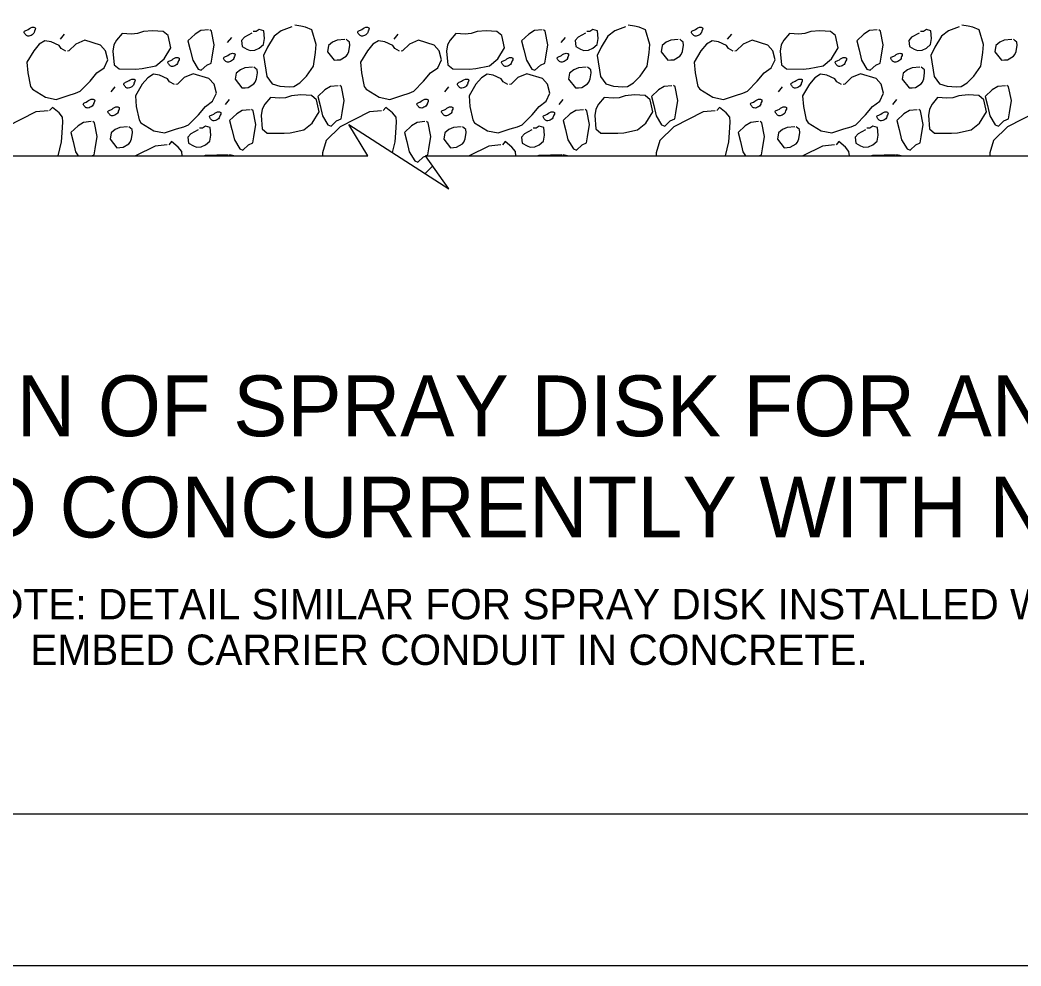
# Model space of a CAD drawing. Extents: x 3239 to 4230, y -4276 to -2494.
# Drawn here: x 3405.7 to 3504.5, y -4276.3 to -4182.9 of the extents above; entities that cross this region are included whole.
import ezdxf

# ---------------------------------------------------------------- set-up
doc = ezdxf.new("R2010")
doc.units = 0
doc.layers.add('2', color=7, linetype='Continuous')
doc.layers.add('PLT-BNDY', color=7, linetype='Continuous')

msp = doc.modelspace()

# ---------------------------------------------------------------- linework, layer by layer
at = {"layer": '2'}
for p, q in [((3440.07, -4196.29), (3438.177, -4193.169)), ((3438.177, -4193.169), (3448.046, -4199.536)), ((3325.856, -4196.29), (3440.07, -4196.29)), ((3448.046, -4199.536), (3445.738, -4196.29)), ((3445.738, -4196.29), (3572.037, -4196.29)), ((3445.705, -4198.026), (3446.446, -4197.285)), ((4065.025, -4261.289), (3279.025, -4261.289))]:
    msp.add_line(p, q, dxfattribs=at)
for points in [[(3432.546, -4183.543), (3431.513, -4183.938), (3430.817, -4184.456), (3430.151, -4185.561), (3429.764, -4186.357), (3430.098, -4188.442), (3430.62, -4189.159), (3431.381, -4189.398), (3432.302, -4189.469), (3432.757, -4189.429), (3433.335, -4189.075), (3434.017, -4188.404), (3434.695, -4187.429), (3434.88, -4186.063), (3434.967, -4185.293), (3434.533, -4183.826), (3433.9, -4183.578), (3433.434, -4183.465), (3432.836, -4183.365)], [(3465.49, -4183.543), (3464.456, -4183.938), (3463.761, -4184.456), (3463.095, -4185.561), (3462.708, -4186.357), (3463.042, -4188.442), (3463.563, -4189.159), (3464.325, -4189.398), (3465.246, -4189.469), (3465.701, -4189.429), (3466.279, -4189.075), (3466.961, -4188.404), (3467.638, -4187.429), (3467.824, -4186.063), (3467.91, -4185.293), (3467.477, -4183.826), (3466.844, -4183.578), (3466.377, -4183.465), (3465.779, -4183.365)], [(3498.433, -4183.543), (3497.4, -4183.938), (3496.705, -4184.456), (3496.039, -4185.561), (3495.651, -4186.357), (3495.985, -4188.442), (3496.507, -4189.159), (3497.269, -4189.398), (3498.189, -4189.469), (3498.645, -4189.429), (3499.223, -4189.075), (3499.905, -4188.404), (3500.582, -4187.429), (3500.768, -4186.063), (3500.854, -4185.293), (3500.42, -4183.826), (3499.788, -4183.578), (3499.321, -4183.465), (3498.723, -4183.365)], [(3410.082, -4184.25), (3409.666, -4184.745)], [(3416.726, -4184.259), (3415.805, -4184.188), (3415.252, -4184.847), (3414.989, -4185.327), (3414.891, -4185.944), (3415.009, -4187.286), (3415.502, -4187.7), (3417.16, -4187.708), (3417.764, -4187.655), (3419.113, -4187.384), (3419.948, -4186.702), (3420.614, -4185.597), (3420.356, -4184.4), (3419.862, -4183.984), (3418.811, -4183.925), (3417.903, -4184.004), (3417.31, -4184.208), (3416.726, -4184.259)], [(3424.313, -4183.849), (3423.554, -4183.915), (3422.998, -4184.269), (3422.293, -4184.92), (3422.523, -4185.814), (3422.766, -4186.839), (3423.299, -4187.708), (3423.615, -4187.832), (3424.158, -4187.328), (3424.601, -4187.135), (3424.7, -4186.539), (3424.897, -4185.301), (3424.628, -4183.975), (3424.464, -4183.835)], [(3426.586, -4184.598), (3426.17, -4185.093)], [(3428.598, -4184.178), (3427.867, -4184.547), (3427.593, -4184.877), (3427.646, -4185.481), (3428.126, -4185.744), (3428.442, -4185.87), (3428.896, -4185.831), (3429.336, -4185.639), (3429.742, -4185.298), (3429.841, -4184.68), (3429.775, -4183.923), (3429.33, -4183.809), (3429.04, -4183.988), (3428.737, -4184.014)], [(3443.026, -4184.25), (3442.61, -4184.745)], [(3449.67, -4184.259), (3448.749, -4184.188), (3448.196, -4184.847), (3447.933, -4185.327), (3447.835, -4185.944), (3447.952, -4187.286), (3448.446, -4187.7), (3450.103, -4187.708), (3450.708, -4187.655), (3452.057, -4187.384), (3452.892, -4186.702), (3453.558, -4185.597), (3453.299, -4184.4), (3452.806, -4183.984), (3451.754, -4183.925), (3450.847, -4184.004), (3450.254, -4184.208), (3449.67, -4184.259)], [(3457.257, -4183.849), (3456.498, -4183.915), (3455.942, -4184.269), (3455.236, -4184.92), (3455.466, -4185.814), (3455.71, -4186.839), (3456.243, -4187.708), (3456.559, -4187.832), (3457.102, -4187.328), (3457.544, -4187.135), (3457.644, -4186.539), (3457.841, -4185.301), (3457.571, -4183.975), (3457.407, -4183.835)], [(3459.53, -4184.598), (3459.114, -4185.093)], [(3461.541, -4184.178), (3460.811, -4184.547), (3460.536, -4184.877), (3460.589, -4185.481), (3461.07, -4185.744), (3461.386, -4185.87), (3461.84, -4185.831), (3462.28, -4185.639), (3462.686, -4185.298), (3462.785, -4184.68), (3462.719, -4183.923), (3462.273, -4183.809), (3461.984, -4183.988), (3461.681, -4184.014)], [(3475.97, -4184.25), (3475.554, -4184.745)], [(3482.613, -4184.259), (3481.693, -4184.188), (3481.14, -4184.847), (3480.876, -4185.327), (3480.779, -4185.944), (3480.896, -4187.286), (3481.389, -4187.7), (3483.047, -4187.708), (3483.651, -4187.655), (3485.001, -4187.384), (3485.836, -4186.702), (3486.501, -4185.597), (3486.243, -4184.4), (3485.75, -4183.984), (3484.698, -4183.925), (3483.791, -4184.004), (3483.198, -4184.208), (3482.613, -4184.259)], [(3490.358, -4183.849), (3489.599, -4183.915), (3489.043, -4184.269), (3488.338, -4184.92), (3488.568, -4185.814), (3488.811, -4186.839), (3489.344, -4187.708), (3489.66, -4187.832), (3490.203, -4187.328), (3490.645, -4187.135), (3490.745, -4186.539), (3490.942, -4185.301), (3490.672, -4183.975), (3490.508, -4183.835)], [(3494.485, -4184.178), (3493.755, -4184.547), (3493.48, -4184.877), (3493.533, -4185.481), (3494.013, -4185.744), (3494.33, -4185.87), (3494.783, -4185.831), (3495.224, -4185.639), (3495.629, -4185.298), (3495.729, -4184.68), (3495.663, -4183.923), (3495.217, -4183.809), (3494.927, -4183.988), (3494.624, -4184.014)], [(3410.251, -4185.945), (3409.77, -4185.681), (3409.592, -4185.393), (3408.795, -4185.004), (3408.178, -4184.906), (3407.62, -4185.261), (3407.066, -4185.918), (3406.4, -4187.022), (3406.493, -4188.082), (3406.765, -4189.432), (3406.94, -4189.7), (3408.23, -4190.501), (3409.295, -4190.714), (3410.48, -4190.304), (3411.202, -4190.089), (3411.643, -4189.899), (3412.625, -4188.919), (3413.294, -4188.098), (3414.011, -4187.578), (3414.398, -4186.782), (3414.17, -4185.907), (3413.663, -4185.341), (3412.119, -4184.867), (3411.236, -4185.25), (3410.532, -4185.92), (3410.403, -4185.931)], [(3437.773, -4184.782), (3437.016, -4184.848), (3436.576, -4185.04), (3436.17, -4185.38), (3436.07, -4185.999), (3436.733, -4186.835), (3437.036, -4186.809), (3437.339, -4186.782), (3437.918, -4186.448), (3438.058, -4186.282), (3438.182, -4185.968), (3438.279, -4185.349), (3438.253, -4185.046), (3438.089, -4184.908), (3437.925, -4184.769)], [(3443.194, -4185.945), (3442.714, -4185.681), (3442.535, -4185.393), (3441.739, -4185.004), (3441.121, -4184.906), (3440.563, -4185.261), (3440.01, -4185.918), (3439.344, -4187.022), (3439.437, -4188.082), (3439.709, -4189.432), (3439.884, -4189.7), (3441.174, -4190.501), (3442.238, -4190.714), (3443.424, -4190.304), (3444.146, -4190.089), (3444.587, -4189.899), (3445.569, -4188.919), (3446.238, -4188.098), (3446.955, -4187.578), (3447.342, -4186.782), (3447.114, -4185.907), (3446.607, -4185.341), (3445.062, -4184.867), (3444.18, -4185.25), (3443.476, -4185.92), (3443.347, -4185.931)], [(3470.716, -4184.782), (3469.96, -4184.848), (3469.519, -4185.04), (3469.114, -4185.38), (3469.014, -4185.999), (3469.676, -4186.835), (3469.979, -4186.809), (3470.283, -4186.782), (3470.862, -4186.448), (3471.001, -4186.282), (3471.126, -4185.968), (3471.223, -4185.349), (3471.197, -4185.046), (3471.033, -4184.908), (3470.869, -4184.769)], [(3476.138, -4185.945), (3475.658, -4185.681), (3475.479, -4185.393), (3474.683, -4185.004), (3474.065, -4184.906), (3473.507, -4185.261), (3472.954, -4185.918), (3472.288, -4187.022), (3472.381, -4188.082), (3472.652, -4189.432), (3472.828, -4189.7), (3474.117, -4190.501), (3475.182, -4190.714), (3476.368, -4190.304), (3477.09, -4190.089), (3477.53, -4189.899), (3478.512, -4188.919), (3479.181, -4188.098), (3479.898, -4187.578), (3480.286, -4186.782), (3480.058, -4185.907), (3479.551, -4185.341), (3478.006, -4184.867), (3477.123, -4185.25), (3476.42, -4185.92), (3476.291, -4185.931)], [(3503.66, -4184.782), (3502.904, -4184.848), (3502.463, -4185.04), (3502.057, -4185.38), (3501.958, -4185.999), (3502.62, -4186.835), (3502.923, -4186.809), (3503.226, -4186.782), (3503.806, -4186.448), (3503.945, -4186.282), (3504.069, -4185.968), (3504.167, -4185.349), (3504.14, -4185.046), (3503.977, -4184.908), (3503.813, -4184.769)], [(3428.668, -4187.521), (3427.911, -4187.587), (3427.469, -4187.779), (3427.04, -4188.099), (3426.942, -4188.718), (3427.626, -4189.574), (3427.929, -4189.548), (3428.232, -4189.521), (3428.812, -4189.165), (3428.927, -4189.002), (3429.053, -4188.685), (3429.151, -4188.068), (3429.126, -4187.786), (3428.963, -4187.649), (3428.797, -4187.51)], [(3461.611, -4187.521), (3460.855, -4187.587), (3460.413, -4187.779), (3459.983, -4188.099), (3459.886, -4188.718), (3460.57, -4189.574), (3460.873, -4189.548), (3461.176, -4189.521), (3461.755, -4189.165), (3461.871, -4189.002), (3461.997, -4188.685), (3462.095, -4188.068), (3462.07, -4187.786), (3461.906, -4187.649), (3461.741, -4187.51)], [(3494.555, -4187.521), (3493.798, -4187.587), (3493.356, -4187.779), (3492.927, -4188.099), (3492.83, -4188.718), (3493.513, -4189.574), (3493.816, -4189.548), (3494.119, -4189.521), (3494.699, -4189.165), (3494.815, -4189.002), (3494.941, -4188.685), (3495.038, -4188.068), (3495.014, -4187.786), (3494.85, -4187.649), (3494.684, -4187.51)], [(3420.951, -4189.242), (3420.471, -4188.979), (3420.292, -4188.689), (3419.497, -4188.323), (3418.88, -4188.225), (3418.322, -4188.58), (3417.767, -4189.215), (3417.103, -4190.341), (3417.196, -4191.401), (3417.465, -4192.729), (3417.642, -4193.019), (3418.93, -4193.799), (3419.995, -4194.011), (3421.181, -4193.602), (3421.905, -4193.409), (3422.345, -4193.216), (3423.325, -4192.216), (3424.016, -4191.393), (3424.711, -4190.874), (3425.101, -4190.099), (3424.871, -4189.205), (3424.364, -4188.638), (3422.819, -4188.186), (3421.936, -4188.545), (3421.254, -4189.216), (3421.102, -4189.229)], [(3453.895, -4189.242), (3453.415, -4188.979), (3453.236, -4188.689), (3452.441, -4188.323), (3451.824, -4188.225), (3451.266, -4188.58), (3450.711, -4189.215), (3450.047, -4190.341), (3450.139, -4191.401), (3450.409, -4192.729), (3450.586, -4193.019), (3451.874, -4193.799), (3452.939, -4194.011), (3454.125, -4193.602), (3454.848, -4193.409), (3455.289, -4193.216), (3456.269, -4192.216), (3456.96, -4191.393), (3457.655, -4190.874), (3458.044, -4190.099), (3457.814, -4189.205), (3457.308, -4188.638), (3455.763, -4188.186), (3454.88, -4188.545), (3454.198, -4189.216), (3454.045, -4189.229)], [(3486.839, -4189.242), (3486.358, -4188.979), (3486.18, -4188.689), (3485.385, -4188.323), (3484.768, -4188.225), (3484.209, -4188.58), (3483.654, -4189.215), (3482.99, -4190.341), (3483.083, -4191.401), (3483.353, -4192.729), (3483.53, -4193.019), (3484.818, -4193.799), (3485.883, -4194.011), (3487.068, -4193.602), (3487.792, -4193.409), (3488.233, -4193.216), (3489.213, -4192.216), (3489.903, -4191.393), (3490.599, -4190.874), (3490.988, -4190.099), (3490.758, -4189.205), (3490.251, -4188.638), (3488.707, -4188.186), (3487.824, -4188.545), (3487.142, -4189.216), (3486.989, -4189.229)], [(3415.092, -4189.474), (3414.677, -4189.969)], [(3437.13, -4189.352), (3436.372, -4189.418), (3435.816, -4189.772), (3435.11, -4190.423), (3435.34, -4191.317), (3435.583, -4192.342), (3436.117, -4193.211), (3436.433, -4193.335), (3436.976, -4192.831), (3437.418, -4192.639), (3437.518, -4192.043), (3437.715, -4190.804), (3437.445, -4189.478), (3437.281, -4189.339)], [(3448.036, -4189.474), (3447.62, -4189.969)], [(3470.074, -4189.352), (3469.316, -4189.418), (3468.759, -4189.772), (3468.054, -4190.423), (3468.284, -4191.317), (3468.527, -4192.342), (3469.06, -4193.211), (3469.377, -4193.335), (3469.92, -4192.831), (3470.362, -4192.639), (3470.461, -4192.043), (3470.658, -4190.804), (3470.389, -4189.478), (3470.225, -4189.339)], [(3480.98, -4189.474), (3480.564, -4189.969)], [(3503.018, -4189.352), (3502.259, -4189.418), (3501.703, -4189.772), (3500.998, -4190.423), (3501.228, -4191.317), (3501.471, -4192.342), (3502.004, -4193.211), (3502.32, -4193.335), (3502.863, -4192.831), (3503.305, -4192.639), (3503.405, -4192.043), (3503.602, -4190.804), (3503.333, -4189.478), (3503.169, -4189.339)], [(3431.354, -4190.598), (3430.434, -4190.527), (3429.881, -4191.186), (3429.618, -4191.666), (3429.52, -4192.283), (3429.637, -4193.625), (3430.13, -4194.039), (3431.788, -4194.047), (3432.392, -4193.994), (3433.742, -4193.723), (3434.577, -4193.041), (3435.243, -4191.936), (3434.984, -4190.739), (3434.491, -4190.323), (3433.439, -4190.264), (3432.532, -4190.343), (3431.939, -4190.547), (3431.354, -4190.598)], [(3464.298, -4190.598), (3463.378, -4190.527), (3462.825, -4191.186), (3462.561, -4191.666), (3462.464, -4192.283), (3462.581, -4193.625), (3463.074, -4194.039), (3464.732, -4194.047), (3465.336, -4193.994), (3466.686, -4193.723), (3467.52, -4193.041), (3468.186, -4191.936), (3467.928, -4190.739), (3467.434, -4190.323), (3466.383, -4190.264), (3465.476, -4190.343), (3464.883, -4190.547), (3464.298, -4190.598)], [(3497.242, -4190.598), (3496.321, -4190.527), (3495.768, -4191.186), (3495.505, -4191.666), (3495.407, -4192.283), (3495.525, -4193.625), (3496.018, -4194.039), (3497.676, -4194.047), (3498.28, -4193.994), (3499.629, -4193.723), (3500.464, -4193.041), (3501.13, -4191.936), (3500.872, -4190.739), (3500.378, -4190.323), (3499.327, -4190.264), (3498.419, -4190.343), (3497.827, -4190.547), (3497.242, -4190.598)], [(3409.48, -4196.29), (3409.814, -4194.896), (3409.887, -4193.995), (3409.947, -4192.922), (3409.907, -4192.469), (3409.564, -4192.041), (3408.907, -4191.51), (3408.629, -4191.818)], [(3426.377, -4190.728), (3425.961, -4191.223)], [(3442.503, -4195.96), (3442.758, -4194.896), (3442.831, -4193.995), (3442.891, -4192.922), (3442.851, -4192.469), (3442.508, -4192.041), (3441.851, -4191.51), (3441.572, -4191.818)], [(3459.321, -4190.728), (3458.905, -4191.223)], [(3475.367, -4196.29), (3475.702, -4194.896), (3475.775, -4193.995), (3475.834, -4192.922), (3475.795, -4192.469), (3475.452, -4192.041), (3474.795, -4191.51), (3474.516, -4191.818)], [(3492.265, -4190.728), (3491.849, -4191.223)], [(3408.478, -4191.831), (3407.289, -4191.935), (3404.388, -4193.409), (3403.002, -4194.751), (3402.653, -4195.98), (3402.651, -4196.29)], [(3428.423, -4191.72), (3427.664, -4191.787), (3427.108, -4192.141), (3426.403, -4192.791), (3426.633, -4193.685), (3426.876, -4194.71), (3427.409, -4195.58), (3427.725, -4195.704), (3428.268, -4195.199), (3428.71, -4195.007), (3428.81, -4194.411), (3429.007, -4193.172), (3428.738, -4191.846), (3428.574, -4191.707)], [(3441.422, -4191.831), (3440.233, -4191.935), (3437.332, -4193.409), (3435.946, -4194.751), (3435.596, -4195.98), (3435.595, -4196.29)], [(3461.367, -4191.72), (3460.608, -4191.787), (3460.052, -4192.141), (3459.346, -4192.791), (3459.576, -4193.685), (3459.82, -4194.71), (3460.353, -4195.58), (3460.669, -4195.704), (3461.212, -4195.199), (3461.654, -4195.007), (3461.754, -4194.411), (3461.951, -4193.172), (3461.681, -4191.846), (3461.517, -4191.707)], [(3474.366, -4191.831), (3473.177, -4191.935), (3470.276, -4193.409), (3468.89, -4194.751), (3468.54, -4195.98), (3468.538, -4196.29)], [(3494.31, -4191.72), (3493.552, -4191.787), (3492.996, -4192.141), (3492.29, -4192.791), (3492.52, -4193.685), (3492.763, -4194.71), (3493.297, -4195.58), (3493.613, -4195.704), (3494.156, -4195.199), (3494.598, -4195.007), (3494.698, -4194.411), (3494.895, -4193.172), (3494.625, -4191.846), (3494.461, -4191.707)], [(3507.309, -4191.831), (3506.12, -4191.935), (3503.219, -4193.409), (3501.833, -4194.751), (3501.484, -4195.98), (3501.482, -4196.29)], [(3412.755, -4192.904), (3411.996, -4192.971), (3411.44, -4193.325), (3410.735, -4193.976), (3410.965, -4194.87), (3411.208, -4195.895), (3411.45, -4196.29)], [(3412.815, -4196.29), (3413.042, -4196.191), (3413.142, -4195.595), (3413.339, -4194.357), (3413.069, -4193.03), (3412.906, -4192.891)], [(3416.317, -4193.42), (3415.561, -4193.486), (3415.12, -4193.678), (3414.715, -4194.017), (3414.615, -4194.637), (3415.277, -4195.473), (3415.58, -4195.447), (3415.883, -4195.42), (3416.463, -4195.086), (3416.602, -4194.92), (3416.727, -4194.606), (3416.824, -4193.986), (3416.798, -4193.683), (3416.634, -4193.546), (3416.47, -4193.407)], [(3423.303, -4193.722), (3422.573, -4194.091), (3422.299, -4194.42), (3422.351, -4195.025), (3422.832, -4195.288), (3423.148, -4195.414), (3423.602, -4195.374), (3424.042, -4195.182), (3424.448, -4194.841), (3424.547, -4194.224), (3424.481, -4193.467), (3424.035, -4193.352), (3423.746, -4193.531), (3423.443, -4193.558)], [(3445.699, -4192.904), (3444.94, -4192.971), (3444.384, -4193.325), (3443.678, -4193.976), (3443.908, -4194.87), (3444.152, -4195.895), (3444.685, -4196.764), (3445.001, -4196.888), (3445.544, -4196.383), (3445.743, -4196.297)], [(3445.759, -4196.29), (3445.986, -4196.191), (3446.086, -4195.595), (3446.283, -4194.357), (3446.013, -4193.03), (3445.849, -4192.891)], [(3449.261, -4193.42), (3448.504, -4193.486), (3448.064, -4193.678), (3447.658, -4194.017), (3447.559, -4194.637), (3448.221, -4195.473), (3448.524, -4195.447), (3448.827, -4195.42), (3449.407, -4195.086), (3449.546, -4194.92), (3449.67, -4194.606), (3449.768, -4193.986), (3449.741, -4193.683), (3449.578, -4193.546), (3449.414, -4193.407)], [(3456.247, -4193.722), (3455.517, -4194.091), (3455.242, -4194.42), (3455.295, -4195.025), (3455.775, -4195.288), (3456.092, -4195.414), (3456.545, -4195.374), (3456.986, -4195.182), (3457.391, -4194.841), (3457.491, -4194.224), (3457.425, -4193.467), (3456.979, -4193.352), (3456.69, -4193.531), (3456.386, -4193.558)], [(3478.642, -4192.904), (3477.884, -4192.971), (3477.328, -4193.325), (3476.622, -4193.976), (3476.852, -4194.87), (3477.095, -4195.895), (3477.338, -4196.29)], [(3478.703, -4196.29), (3478.93, -4196.191), (3479.03, -4195.595), (3479.227, -4194.357), (3478.957, -4193.03), (3478.793, -4192.891)], [(3482.205, -4193.42), (3481.448, -4193.486), (3481.008, -4193.678), (3480.602, -4194.017), (3480.503, -4194.637), (3481.165, -4195.473), (3481.468, -4195.447), (3481.771, -4195.42), (3482.351, -4195.086), (3482.49, -4194.92), (3482.614, -4194.606), (3482.712, -4193.986), (3482.685, -4193.683), (3482.521, -4193.546), (3482.357, -4193.407)], [(3489.191, -4193.722), (3488.461, -4194.091), (3488.186, -4194.42), (3488.239, -4195.025), (3488.719, -4195.288), (3489.035, -4195.414), (3489.489, -4195.374), (3489.929, -4195.182), (3490.335, -4194.841), (3490.435, -4194.224), (3490.368, -4193.467), (3489.923, -4193.352), (3489.633, -4193.531), (3489.33, -4193.558)], [(3420.253, -4195.208), (3419.063, -4195.312), (3417.111, -4196.29)], [(3421.718, -4196.29), (3421.719, -4196.28), (3421.681, -4195.846), (3421.34, -4195.418), (3420.681, -4194.865), (3420.404, -4195.195)], [(3453.197, -4195.208), (3452.007, -4195.312), (3450.055, -4196.29)], [(3454.662, -4196.29), (3454.662, -4196.28), (3454.624, -4195.846), (3454.283, -4195.418), (3453.624, -4194.865), (3453.348, -4195.195)], [(3486.141, -4195.208), (3484.95, -4195.312), (3482.999, -4196.29)], [(3487.606, -4196.29), (3487.606, -4196.28), (3487.568, -4195.846), (3487.227, -4195.418), (3486.568, -4194.865), (3486.292, -4195.195)], [(3426.265, -4196.185), (3424.004, -4196.232), (3423.915, -4196.29)], [(3426.829, -4196.29), (3426.416, -4196.172), (3426.334, -4196.29)], [(3459.209, -4196.185), (3456.947, -4196.232), (3456.859, -4196.29)], [(3459.773, -4196.29), (3459.36, -4196.172), (3459.277, -4196.29)], [(3492.153, -4196.185), (3489.891, -4196.232), (3489.803, -4196.29)], [(3492.716, -4196.29), (3492.304, -4196.172), (3492.221, -4196.29)]]:
    msp.add_lwpolyline(points, dxfattribs=at)
for points in [[(3407.135, -4183.977), (3407.064, -4184.178), (3406.903, -4184.324), (3406.479, -4184.448), (3406.223, -4184.273), (3406.114, -4184.023), (3406.384, -4183.867), (3406.903, -4183.581), (3407.214, -4183.643), (3407.115, -4184)], [(3440.078, -4183.977), (3440.008, -4184.178), (3439.847, -4184.324), (3439.422, -4184.448), (3439.167, -4184.273), (3439.058, -4184.023), (3439.328, -4183.867), (3439.847, -4183.581), (3440.158, -4183.643), (3440.059, -4184)], [(3473.022, -4183.977), (3472.951, -4184.178), (3472.791, -4184.324), (3472.366, -4184.448), (3472.11, -4184.273), (3472.002, -4184.023), (3472.272, -4183.867), (3472.791, -4183.581), (3473.101, -4183.643), (3473.003, -4184)], [(3421.34, -4186.972), (3421.269, -4187.173), (3421.108, -4187.319), (3420.684, -4187.443), (3420.428, -4187.269), (3420.319, -4187.018), (3420.59, -4186.862), (3421.108, -4186.577), (3421.419, -4186.638), (3421.32, -4186.995)], [(3426.843, -4186.554), (3426.772, -4186.755), (3426.611, -4186.901), (3426.187, -4187.025), (3425.931, -4186.851), (3425.823, -4186.6), (3426.093, -4186.444), (3426.612, -4186.159), (3426.922, -4186.22), (3426.823, -4186.578)], [(3454.284, -4186.972), (3454.213, -4187.173), (3454.052, -4187.319), (3453.627, -4187.443), (3453.372, -4187.269), (3453.263, -4187.018), (3453.533, -4186.862), (3454.052, -4186.577), (3454.363, -4186.638), (3454.264, -4186.995)], [(3459.787, -4186.554), (3459.716, -4186.755), (3459.555, -4186.901), (3459.131, -4187.025), (3458.875, -4186.851), (3458.766, -4186.6), (3459.036, -4186.444), (3459.555, -4186.159), (3459.866, -4186.22), (3459.767, -4186.578)], [(3487.227, -4186.972), (3487.157, -4187.173), (3486.996, -4187.319), (3486.571, -4187.443), (3486.316, -4187.269), (3486.207, -4187.018), (3486.477, -4186.862), (3486.996, -4186.577), (3487.307, -4186.638), (3487.208, -4186.995)], [(3492.731, -4186.554), (3492.66, -4186.755), (3492.499, -4186.901), (3492.074, -4187.025), (3491.819, -4186.851), (3491.71, -4186.6), (3491.98, -4186.444), (3492.499, -4186.159), (3492.81, -4186.22), (3492.711, -4186.578)], [(3416.972, -4189.09), (3416.904, -4189.313), (3416.742, -4189.459), (3416.296, -4189.584), (3416.064, -4189.408), (3415.953, -4189.157), (3416.221, -4188.98), (3416.744, -4188.718), (3417.051, -4188.756), (3416.952, -4189.113)], [(3449.915, -4189.09), (3449.848, -4189.313), (3449.686, -4189.459), (3449.24, -4189.584), (3449.007, -4189.408), (3448.897, -4189.157), (3449.165, -4188.98), (3449.688, -4188.718), (3449.995, -4188.756), (3449.896, -4189.113)], [(3482.859, -4189.09), (3482.792, -4189.313), (3482.629, -4189.459), (3482.183, -4189.584), (3481.951, -4189.408), (3481.841, -4189.157), (3482.109, -4188.98), (3482.631, -4188.718), (3482.938, -4188.756), (3482.84, -4189.113)], [(3412.986, -4191.082), (3412.915, -4191.283), (3412.755, -4191.429), (3412.33, -4191.553), (3412.074, -4191.379), (3411.966, -4191.128), (3412.236, -4190.972), (3412.755, -4190.687), (3413.065, -4190.748), (3412.967, -4191.105)], [(3415.419, -4191.848), (3415.348, -4192.05), (3415.187, -4192.196), (3414.763, -4192.319), (3414.507, -4192.145), (3414.398, -4191.894), (3414.668, -4191.739), (3415.187, -4191.453), (3415.498, -4191.514), (3415.399, -4191.872)], [(3445.93, -4191.082), (3445.859, -4191.283), (3445.698, -4191.429), (3445.274, -4191.553), (3445.018, -4191.379), (3444.909, -4191.128), (3445.18, -4190.972), (3445.698, -4190.687), (3446.009, -4190.748), (3445.91, -4191.105)], [(3448.363, -4191.848), (3448.292, -4192.05), (3448.131, -4192.196), (3447.706, -4192.319), (3447.451, -4192.145), (3447.342, -4191.894), (3447.612, -4191.739), (3448.131, -4191.453), (3448.442, -4191.514), (3448.343, -4191.872)], [(3478.874, -4191.082), (3478.803, -4191.283), (3478.642, -4191.429), (3478.217, -4191.553), (3477.962, -4191.379), (3477.853, -4191.128), (3478.123, -4190.972), (3478.642, -4190.687), (3478.953, -4190.748), (3478.854, -4191.105)], [(3481.306, -4191.848), (3481.235, -4192.05), (3481.075, -4192.196), (3480.65, -4192.319), (3480.394, -4192.145), (3480.286, -4191.894), (3480.556, -4191.739), (3481.075, -4191.453), (3481.386, -4191.514), (3481.287, -4191.872)], [(3425.45, -4192.336), (3425.379, -4192.537), (3425.218, -4192.683), (3424.794, -4192.807), (3424.538, -4192.632), (3424.429, -4192.382), (3424.699, -4192.226), (3425.218, -4191.941), (3425.529, -4192.002), (3425.43, -4192.359)], [(3458.394, -4192.336), (3458.323, -4192.537), (3458.162, -4192.683), (3457.737, -4192.807), (3457.482, -4192.632), (3457.373, -4192.382), (3457.643, -4192.226), (3458.162, -4191.941), (3458.473, -4192.002), (3458.374, -4192.359)], [(3491.337, -4192.336), (3491.266, -4192.537), (3491.106, -4192.683), (3490.681, -4192.807), (3490.426, -4192.632), (3490.317, -4192.382), (3490.587, -4192.226), (3491.106, -4191.941), (3491.417, -4192.002), (3491.318, -4192.359)]]:
    msp.add_spline(points, degree=3, dxfattribs=at)
at = {"layer": 'PLT-BNDY'}
msp.add_lwpolyline([(3239.025, -3682.289), (4080.025, -3682.289), (4080.025, -4276.289), (3239.025, -4276.289)], close=True, dxfattribs=at)

# ---------------------------------------------------------------- texts
at = {"layer": '2'}
for s, height, p in [('INSTALLATION OF SPRAY DISK FOR ANTI-ICING SYSTEM', 6, (3354.095, -4223.967)), ('(SPRAY DISK INSTALLED CONCURRENTLY WITH NEW BITUMINOUS OVERLAY)', 6, (3310.631, -4233.967)), ('NOTE: DETAIL SIMILAR FOR SPRAY DISK INSTALLED WITH EXISTING OVERLAY.', 3, (3400.036, -4242.057)), ('      EMBED CARRIER CONDUIT IN CONCRETE.', 3, (3400.036, -4246.557))]:
    msp.add_text(s, height=height, dxfattribs=at).set_placement(p)

doc.saveas('drawing.dxf')
